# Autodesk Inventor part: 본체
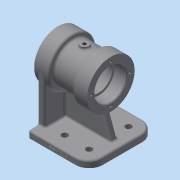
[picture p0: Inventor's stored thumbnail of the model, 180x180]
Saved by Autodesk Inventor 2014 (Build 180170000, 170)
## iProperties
Created: 2020-06
Part Number: 본체
Material: Generic
Document SubType Name: Modeling
Designer: kh
Density: 1 g/cm^3
Appearance: Default
Author: kh
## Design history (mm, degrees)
sketch "Sketch1"
  geometry: L1 (45, -49)-(-45, -49); L2 (-45, -49)-(-45, 49); L3 (-45, 49)-(45, 49); L4 (45, 49)-(45, -49); L5 (45, -49)-(-45, 49); L6 (-45, -49)-(45, 49); 1 further point
  constraints: 12 end point, 2 midpoint, 2 parallel, 1 horizontal, 1 perpendicular
  dimensions: "d0" = 90 distance between parallel lines of L2 L4; "d1" = 98 distance between parallel lines of L3 L1
extrude "Extrusion1" new body sketch "Sketch1" distance "d2" = 10; taper "d3" = 0 deg
sketch "Sketch3"
  geometry: L1 (45, 0)-(45, -10) reference; L2 (45, -10)-(-45, -10) reference; L3 (-45, -10)-(-45, 0) reference; L4 (-45, 0)-(45, 0) reference; L5 (45, 0)-(-45, 0) reference; L6 (45, 0)-(45, -10) reference; L7 (45, -10)-(-45, -10) reference; L8 (-45, -10)-(-45, 0) reference; L9 (-45, 0)-(45, 0) reference; L10 (-61.724, 70)-(61.724, 70); L11 (-50, 70)-(-50, 105); L12 (-50, 105)-(-28, 105); L13 (-28, 105)-(-28, 99); L14 (-28, 99)-(6, 99); L15 (6, 99)-(6, 105); L16 (6, 105)-(28, 105); L17 (28, 105)-(28, 70); 5 further points
  constraints: 16 end point, 4 midpoint, 4 parallel, 2 point on line, 1 collinear, 1 perpendicular, 1 vertical alignment
  dimensions: "d16" = 35 distance of L11.start L11.end; "d17" = 22 distance of L11.end L12.end; "d19" = 34 distance of L13.end L14.end; "d21" = 22 distance of L15.end L16.end; "d22" = 35 distance of L16.end L17.end; "d46" = 80 distance from line of L2 point (0, 70); "d47" = 58 diameter of L14 L10
revolve "Revolution1" sketch "Sketch3" stored, may be unused: angle "d12" = 90 deg
sketch "Sketch6"
  geometry: L1 (45, 0)-(45, -10) reference; L2 (45, -10)-(-45, -10) reference; L3 (-45, -10)-(-45, 0) reference; L4 (-45, 0)-(45, 0) reference; L5 (-50, 35)-(-50, 105) reference; L6 (-50, 105)-(-28, 105) reference; L7 (-28, 105)-(-28, 99) reference; L8 (-28, 99)-(6, 99) reference; L9 (6, 99)-(6, 105) reference; L10 (6, 105)-(28, 105) reference; L11 (28, 105)-(28, 35) reference; L12 (28, 35)-(6, 35) reference; L13 (6, 35)-(6, 41) reference; L14 (6, 41)-(-28, 41) reference; L15 (-28, 41)-(-28, 35) reference; L16 (-28, 35)-(-50, 35) reference; L17 (-45, 0)-(-45, 70); L18 (-45, 70)-(-35, 70); L19 (-35, 70)-(-35, 0); 1 further point
  constraints: 6 end point, 2 perpendicular, 1 parallel, 1 point on line
  dimensions: "d24" = 10 distance of L17.end L18.end; "d35" = 70 distance between parallel lines of L4 L18
extrude "Extrusion2" join sketch "Sketch6" stored distance "d25" = 70; taper "d26" = 0 deg
sketch "Sketch7"
  geometry: L1 (12.753, 55.628)-(33, 0); L2 (45, 0)-(45, -10) reference; L3 (45, -10)-(-45, -10) reference; L4 (-45, -10)-(-45, 35) reference; L5 (-45, 35)-(-50, 35) reference; L6 (-50, 35)-(-50, 105) reference; L7 (-50, 105)-(-28, 105) reference; L8 (-28, 105)-(-28, 99) reference; L9 (-28, 99)-(6, 99) reference; L10 (6, 99)-(6, 105) reference; L11 (6, 105)-(28, 105) reference; L12 (28, 105)-(28, 35) reference; L13 (28, 35)-(6, 35) reference; L14 (6, 35)-(6, 41) reference; L15 (6, 41)-(-28, 41) reference; L16 (-28, 41)-(-28, 35) reference; L17 (-28, 35)-(-35, 35) reference; L18 (-35, 35)-(-35, 0) reference; L19 (-35, 0)-(45, 0) reference; 1 further point
  constraints: 2 end point, 1 point on line
  dimensions: "d27" = 70 deg angle of L19 L1; "d28" = 12 distance of L2.start L1.end
feature "Rib1" sketch "Sketch7" dims "d29" = 1, "d30" = 10, "d31" = 0, "d32" = 0, "d33" = 1, "d34" = 1
sketch "Sketch8"
  geometry: L1 (45, -10)-(-45, -10) reference; L2 (-45, -10)-(-45, 35) reference; L3 (-45, 35)-(-50, 35) reference; L4 (-50, 35)-(-50, 105) reference; L5 (-50, 105)-(-28, 105) reference; L6 (-28, 105)-(-28, 99) reference; L7 (-28, 99)-(6, 99) reference; L8 (6, 99)-(6, 105) reference; L9 (6, 105)-(28, 105) reference; L10 (28, 105)-(28, 35) reference; L11 (28, 35)-(20.261, 35) reference; L12 (20.261, 35)-(33, 0) reference; L13 (33, 0)-(45, 0) reference; L14 (45, 0)-(45, -10) reference; L15 (-50, 70)-(28, 70); L16 (-50, 70)-(-50, 93.5); L17 (-50, 93.5)-(-32, 93.5); L18 (-32, 93.5)-(-32, 90); L19 (-32, 90)-(-26, 90); L20 (-26, 90)-(-26, 93.5); L21 (-26, 93.5)-(4, 93.5); L22 (4, 93.5)-(4, 90); L23 (4, 90)-(10, 90); L24 (10, 90)-(10, 93.5); L25 (10, 93.5)-(28, 93.5); L26 (28, 70)-(28, 93.5); 1 further point
  constraints: 24 end point, 6 perpendicular, 3 parallel, 2 midpoint, 2 point on line, 1 collinear
  dimensions: "d36" = 23.5 distance of L15.start L16.end; "d37" = 18 distance of L16.end L17.end; "d38" = 3.5 distance of L17.end L18.end; "d39" = 6 distance of L18.end L19.end; "d40" = 3.5 distance of L19.end L20.end; "d41" = 30 distance of L20.end L21.end; "d42" = 3.5 distance of L21.end L22.end; "d43" = 6 distance of L22.end L23.end; "d44" = 3.5 distance of L23.end L24.end
revolve "Revolution2" sketch "Sketch8" stored, may be unused: angle "d45" = 90 deg
workplane "Work Plane1"
sketch "Sketch9"
  geometry: L1 (6, -14.177)-(6, 14.177) reference; L2 (6, 14.177)-(28, 14.177) reference; L3 (28, 14.177)-(28, -14.177) reference; L4 (28, -14.177)-(6, -14.177) reference; L5 (-28, 14.177)-(-28, -14.177) reference; L6 (-28, -14.177)-(-50, -14.177) reference; L7 (-50, -14.177)-(-50, 14.177) reference; L8 (-50, 14.177)-(-28, 14.177) reference; C1 r 6 at (-11, 0); 1 further point
  constraints: 1 centre point
  dimensions: "d49" = 12 diameter of C1; "d50" = 39 distance from line of C1.centre L7
extrude "Extrusion3" join sketch "Sketch9" stored distance "d51" = 70; taper "d52" = 0 deg
hole "Hole1" diameter "d55" = 5.188; stored, may be unused: countersink angle "d59" = 90 deg, drill point angle "d61" = 118 deg; dims "d56" = 6, "d57" = 4, "d58" = 2, "d60" = 8, "d106" = 10, "d107" = 10
sketch "Sketch10"
  geometry: C1 r 23.5 at (0, 0) reference; 2 further points
  constraints: 1 vertical alignment
  dimensions: "d64" = 28.5 distance of C1.centre point (0, 28.5)
hole "Hole2" sketch "Sketch10" at (0, 28.5) diameter "d65" = 3.459; stored, may be unused: countersink angle "d69" = 90 deg, drill point angle "d71" = 118 deg; dims "d66" = 10, "d67" = 4, "d68" = 2, "d70" = 12
pattern_circular "Circular Pattern1" dims angle "d73" = 360 deg
workplane "Work Plane2"
mirror "Mirror1"
fillet "Fillet1" dims "d75" = 20
hole "Hole3" diameter "d78" = 9; stored, may be unused: countersink angle "d82" = 90 deg, drill point angle "d84" = 118 deg; dims "d76" = 10, "d77" = 10, "d79" = 10, "d80" = 4, "d81" = 2, "d83" = 12
pattern_linear "Rectangular Pattern1" dims "d89" = 36
fillet "Fillet2" dims "d90" = 3
fillet "Fillet3" dims "d91" = 3
fillet "Fillet4" dims "d92" = 3
fillet "Fillet5" dims "d93" = 3
fillet "Fillet6" dims "d94" = 3
chamfer "Chamfer1" distance "d95" = 1; stored, may be unused: second distance "d96" = 2, angle "d97" = 45 deg
chamfer "Chamfer2" distance "d98" = 1; stored, may be unused: second distance "d99" = 2, angle "d100" = 45 deg
fillet "Fillet7" dims "d101" = 0.3
sketch "Sketch11"
  geometry: L1 (0, 0)-(-67, 0) reference; L2 (0, 0)-(-67, 0) reference; L3 (-67, 7)-(-67, 0) reference; L4 (0, 7)-(-67, 7) reference; L5 (0, 7)-(0, 0) reference; L6 (-70, 7)-(-70, 0) reference; 2 further points
  constraints: 1 other
  dimensions: "d102" = 4 distance from line of L1 point (-25, 4); "d103" = 45 distance from line of L6 point (-25, 4)
emboss "Emboss1" sketch "Sketch11" dims "d0" = 90, "d1" = 98, "d104" = 0.5, "d105" = 0
body "Solid1"
node "Project Cut Edges1"
node "Project Cut Edges2"
node "Project Cut Edges3"
node "Project Cut Edges4"
node "Project Cut Edges5"
node "Project Cut Edges6"
node "Project Cut Edges7"
other parameters: "d48" = 102
